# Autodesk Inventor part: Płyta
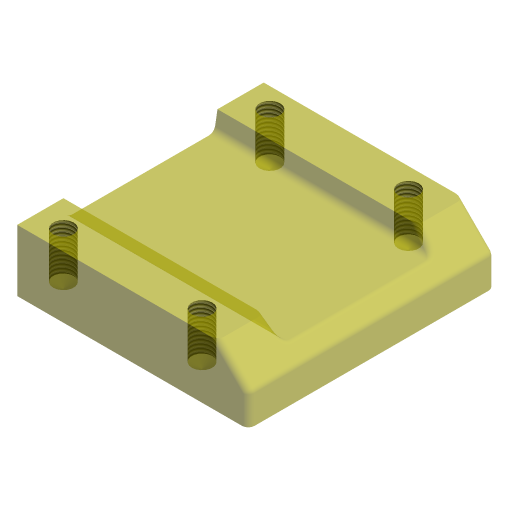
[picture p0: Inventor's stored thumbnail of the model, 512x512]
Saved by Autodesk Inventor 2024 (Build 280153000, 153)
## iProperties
Company: ATC
Shininess: 0.0
Length Units: 11269
Angle Units: 11279
Time Units: 11290
Mass Units: 11283
Length Display Precision: 3
Angle Display Precision: 2
Compacted: True
Created: 2023-03
Part Number: Płyta
Document SubType Name: Modeling
Designer: Andrzej Jaskulski
Material: Kurs-AJ
Density: 1 g/cm^3
Mass: 93.8862 g
Surface Area: 190.314 cm^2
Volume: 93.8862 cm^3
Appearance: Przezroczyste — żółte
Checked By: A.J.
Engr Approved By: Andrzej Jaskulski
Mfg Approved By: Andrzej Jaskulski
Authority: A.J.
Density: 0.0
Volumn: 0.0
Area: 0.0
PropertySet Name: Model Information
Control State: 0
Master: False
Checked Out: False
Title: A.J.: Kurs R2024-MEP
Author: Andrzej Jaskulski
Revision Number: 1/24
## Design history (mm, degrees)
node "Extrusion1" dims "d0" = 0, "d1" = 20
node "Chamfer1" dims "d4" = 10, "d5" = 10, "d29" = 45 deg
node "Extrusion2" dims "d6" = 0, "d7" = 10
node "Fillet1" dims "d11" = 2, "d12" = 2
node "Hole1" dims "d17" = 118 deg, "d18" = 60 deg, "d19" = 2, "d20" = 4, "d21" = 15, "d22" = 6.64, "d28" = 6
node "Bryła1"
node "Korpusy bryłowe"
node "Korpusy powierzchniowe"
sketch "Sketch2"
  geometry: L1 (-60, 0)-(20, 0); L2 (20, 0)-(20, 75) reference; L3 (20, 75)-(-60, 75) reference; L4 (-60, 75)-(-60, 0)
  constraints: 8 end point, 2 parallel, 1 horizontal, 1 perpendicular, 1 vertical
  dimensions: "d3" = 80 distance of L1.start L1.end (= ROZSTAW); "d2" = 75 distance of L1.end L2.end
sketch "Sketch3"
  geometry: L1 (0, -20)-(80, -20) reference; L2 (80, 0)-(0, 0) reference; L3 (15, -20)-(16.058, -14); L4 (16.058, -14)-(63.942, -14); L5 (63.942, -14)-(65, -20); L6 (40, -14)-(40, -20)
  constraints: 8 end point, 2 midpoint, 2 point on line, 1 equal length, 1 parallel, 1 vertical
  dimensions: "d9" = 6 distance between parallel lines of L1 L4; "d8" = 100 deg angle of L4 L3; "d10" = 15 distance of L3.start L1.start; "d23" = 15 distance of L5.end L1.end
sketch "Sketch4"
  geometry: L1 (-53.5, 66.5)-(13.5, 66.5); L2 (13.5, 66.5)-(13.5, 21.5); L3 (13.5, 21.5)-(-53.5, 21.5); L4 (-53.5, 21.5)-(-53.5, 66.5); L5 (-42.264, 75)-(2.264, 75) reference; L6 (20, 75)-(20, 12.828) reference
  constraints: 8 end point, 2 parallel, 1 horizontal, 1 perpendicular
  dimensions: "d15" = 8.5 distance between parallel lines of L5 L1 (= odstęp2); "d14" = 6.5 distance between parallel lines of L2 L6 (= d26); "d16" = 67 distance of L1.start L1.end (= ROZSTAW - 2 x odstęp); "d13" = 45 distance between parallel lines of L3 L1 (= d25)
other parameters: "d25" = 45, "d26" = 6.5, "d27" = 8.5, "odstęp" = 6.5 [user parameter; used in 1 equation term], "ROZSTAW" = 80 [user parameter; used in 2 equation terms], "odstęp2" = 8.5 [user parameter; used in 1 equation term]
